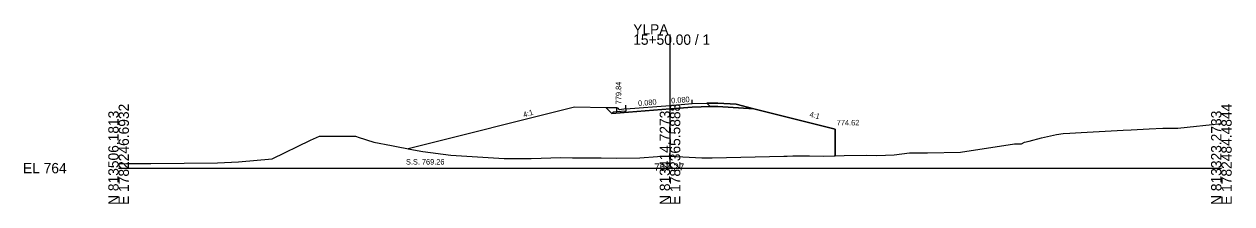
# Model space of a CAD drawing. Extents: x -76 to 1303, y -10 to 9544.
# Drawn here: x -25.7 to 302.8, y 5490.3 to 5539.1 of the extents above; entities that cross this region are included whole.
import ezdxf

# ---------------------------------------------------------------- set-up
doc = ezdxf.new("R2010")
doc.units = 0
for name, color, linetype in [('Exist Cross Section Cell', 7, 'Continuous'), ('Exist XS Center Line Elevation Label', 7, 'Continuous'), ('Exist XS Ground Line', 7, 'Continuous'), ('Prop XS Ditch Standard Text', 7, 'Continuous'), ('Prop XS Dump Level', 7, 'Continuous'), ('Prop XS Earthwork Shape', 7, 'Continuous'), ('Prop XS EOT Tick Mark', 7, 'Continuous'), ('Prop XS Finish Grade', 7, 'Continuous'), ('Prop XS Finish Grade CurbGutter', 7, 'Continuous'), ('Prop XS Finish Grade Earthwork', 7, 'Continuous'), ('Prop XS Finish Grade Paved Shoulder', 7, 'Continuous'), ('Prop XS Finish Grade Pavement', 7, 'Continuous'), ('Prop XS Hydro Elevations', 7, 'Continuous'), ('Prop XS Pvmt Edge Slope', 7, 'Continuous'), ('Prop XS SE Text', 7, 'Continuous'), ('Prop XS Side Slope Text', 7, 'Continuous'), ('Prop XS SS Elevation Text', 7, 'Continuous'), ('Prop XS Subgrade CurbGutter', 7, 'Continuous'), ('Prop XS Subgrade Earthwork', 7, 'Continuous'), ('Scratch_Level_3', 7, 'Continuous')]:
    doc.layers.add(name, color=color, linetype=linetype)

msp = doc.modelspace()

# ---------------------------------------------------------------- linework, layer by layer
at = {"layer": 'Exist Cross Section Cell'}
for p, q in [((150, 5500), (150, 5536.3)), ((0, 5500), (150, 5500)), ((150, 5500), (300, 5500))]:
    msp.add_line(p, q, dxfattribs=at)
at = {"layer": 'Exist XS Ground Line'}
for p, q in [((256.92, 5509.44), (258.78, 5509.54)), ((258.78, 5509.54), (261.81, 5509.67)), ((261.81, 5509.67), (273.27, 5510.29)), ((273.27, 5510.29), (275.48, 5510.38)), ((275.48, 5510.38), (280.32, 5510.7)), ((280.32, 5510.7), (284.08, 5510.81)), ((284.08, 5510.81), (288.15, 5510.88)), ((288.15, 5510.88), (300, 5512.1)), ((41.74, 5502.55), (52.24, 5507.59)), ((52.24, 5507.59), (54.61, 5508.71)), ((54.61, 5508.71), (61.86, 5508.71)), ((61.86, 5508.71), (63.69, 5508.7)), ((63.69, 5508.7), (64.43, 5508.7)), ((64.43, 5508.7), (64.75, 5508.57)), ((64.75, 5508.57), (65.2, 5508.42)), ((65.2, 5508.42), (69.47, 5507.03)), ((69.47, 5507.03), (74.22, 5506.14)), ((229.04, 5504.33), (243.68, 5506.61)), ((243.68, 5506.61), (245.62, 5506.64)), ((245.62, 5506.64), (246.41, 5507.03)), ((246.41, 5507.03), (247.68, 5507.33)), ((247.68, 5507.33), (251.09, 5508.22)), ((251.09, 5508.22), (255.13, 5509.13)), ((255.13, 5509.13), (256.92, 5509.44)), ((74.22, 5506.14), (80.22, 5504.98)), ((80.22, 5504.98), (82.73, 5504.51)), ((82.73, 5504.51), (90.39, 5503.56)), ((90.39, 5503.56), (104.91, 5502.66)), ((141.76, 5502.81), (146.6, 5503.19)), ((146.6, 5503.19), (149.46, 5503.3)), ((149.46, 5503.3), (150, 5503.27)), ((150, 5503.27), (158.63, 5502.82)), ((161.5, 5502.76), (181, 5503.28)), ((181, 5503.28), (181.88, 5503.29)), ((181.88, 5503.29), (183.37, 5503.33)), ((183.37, 5503.33), (185.74, 5503.36)), ((185.74, 5503.36), (186.65, 5503.34)), ((186.65, 5503.34), (187.93, 5503.36)), ((187.93, 5503.36), (191.81, 5503.29)), ((191.81, 5503.29), (197.41, 5503.42)), ((197.41, 5503.42), (203.45, 5503.54)), ((203.45, 5503.54), (206.3, 5503.43)), ((206.3, 5503.43), (211, 5503.64)), ((211, 5503.64), (215.19, 5504.15)), ((215.19, 5504.15), (220.07, 5504.19)), ((220.07, 5504.19), (229.04, 5504.33)), ((0, 5501.13), (2.18, 5501.3)), ((2.18, 5501.3), (4.11, 5501.29)), ((4.11, 5501.29), (8.77, 5501.26)), ((8.77, 5501.26), (26.94, 5501.41)), ((26.94, 5501.41), (32.66, 5501.69)), ((32.66, 5501.69), (41.74, 5502.55)), ((104.91, 5502.66), (112.19, 5502.6)), ((112.19, 5502.6), (120.31, 5502.91)), ((120.31, 5502.91), (123.44, 5502.82)), ((123.44, 5502.82), (128.06, 5502.82)), ((128.06, 5502.82), (131.3, 5502.8)), ((131.3, 5502.8), (135.47, 5502.67)), ((135.47, 5502.67), (141.76, 5502.81)), ((158.63, 5502.82), (160.12, 5502.8)), ((160.12, 5502.8), (161.5, 5502.76))]:
    msp.add_line(p, q, dxfattribs=at)
at = {"layer": 'Prop XS Dump Level'}
for p, q in [((138, 5516.08), (150, 5517.04)), ((150, 5517.04), (156, 5517.52))]:
    msp.add_line(p, q, dxfattribs=at)
at = {"layer": 'Prop XS Earthwork Shape'}
msp.add_lwpolyline([(128.06, 5502.82), (131.3, 5502.8), (135.47, 5502.67), (141.76, 5502.81), (146.6, 5503.19), (149.46, 5503.3), (150, 5503.27), (158.63, 5502.82), (160.12, 5502.8), (161.5, 5502.76), (181, 5503.28), (181.88, 5503.29), (183.37, 5503.33), (185.74, 5503.36), (186.65, 5503.34), (187.93, 5503.36), (191.81, 5503.29), (194.95, 5503.36), (194.95, 5510.62), (172.83, 5516.15), (162.98, 5516.74), (160.9, 5516.7), (156.05, 5516.6), (150.07, 5516.12), (134.16, 5514.85), (132.61, 5516.4), (124, 5516.58), (78.74, 5505.26), (80.22, 5504.98), (82.73, 5504.51), (90.39, 5503.56), (104.91, 5502.66), (112.19, 5502.6), (120.31, 5502.91), (123.44, 5502.82)], close=True, dxfattribs=at)
at = {"layer": 'Prop XS EOT Tick Mark'}
for p, q in [((138, 5516.08), (138, 5517.08)), ((156, 5517.52), (156, 5518.52))]:
    msp.add_line(p, q, dxfattribs=at)
at = {"layer": 'Prop XS Finish Grade'}
for p, q in [((135.5, 5516.34), (132.61, 5516.4)), ((160, 5517.6), (163, 5517.66)), ((163, 5517.66), (168, 5517.36)), ((168, 5517.36), (172.83, 5516.15))]:
    msp.add_line(p, q, dxfattribs=at)
at = {"layer": 'Prop XS Finish Grade CurbGutter'}
for p, q in [((135.5, 5516.34), (135.75, 5516.34)), ((135.75, 5516.34), (135.88, 5516.32)), ((135.97, 5516.23), (135.88, 5516.32)), ((136.03, 5515.98), (135.97, 5516.23)), ((138, 5516.08), (136.25, 5515.87)), ((136.13, 5515.89), (136.03, 5515.98)), ((136.25, 5515.87), (136.13, 5515.89))]:
    msp.add_line(p, q, dxfattribs=at)
at = {"layer": 'Prop XS Finish Grade Earthwork'}
for p, q in [((124, 5516.58), (78.74, 5505.26)), ((132.61, 5516.4), (124, 5516.58)), ((172.83, 5516.15), (194.95, 5510.62)), ((194.95, 5510.62), (194.95, 5503.36))]:
    msp.add_line(p, q, dxfattribs=at)
at = {"layer": 'Prop XS Finish Grade Paved Shoulder'}
msp.add_line((156, 5517.52), (160, 5517.6), dxfattribs=at)
at = {"layer": 'Prop XS Finish Grade Pavement'}
for p, q in [((138, 5516.08), (150, 5517.04)), ((150, 5517.04), (156, 5517.52))]:
    msp.add_line(p, q, dxfattribs=at)
at = {"layer": 'Prop XS Pvmt Edge Slope'}
for p, q in [((160, 5517.6), (160.9, 5516.7)), ((134.5, 5515.22), (134.16, 5514.85)), ((135.5, 5515.3), (134.5, 5515.22))]:
    msp.add_line(p, q, dxfattribs=at)
at = {"layer": 'Prop XS Subgrade CurbGutter'}
for p, q in [((135.5, 5515.3), (135.5, 5516.34)), ((138, 5516.08), (138, 5515.5)), ((138, 5515.5), (135.5, 5515.3))]:
    msp.add_line(p, q, dxfattribs=at)
at = {"layer": 'Prop XS Subgrade Earthwork'}
for p, q in [((134.16, 5514.85), (132.61, 5516.4)), ((134.16, 5514.85), (150.07, 5516.12)), ((150.07, 5516.12), (156.05, 5516.6)), ((156.05, 5516.6), (160.9, 5516.7)), ((160.9, 5516.7), (162.98, 5516.74)), ((162.98, 5516.74), (172.83, 5516.15))]:
    msp.add_line(p, q, dxfattribs=at)
at = {"layer": 'Scratch_Level_3'}
for p, q in [((163, 5517.66), (160, 5517.6)), ((160, 5517.6), (160.9, 5516.7)), ((160.9, 5516.7), (162.98, 5516.74)), ((162.98, 5516.74), (172.83, 5516.15)), ((168, 5517.36), (163, 5517.66)), ((172.83, 5516.15), (168, 5517.36))]:
    msp.add_line(p, q, dxfattribs=at)

# ---------------------------------------------------------------- texts
at = {"layer": 'Exist Cross Section Cell'}
for s, p in [('YLPA', (140, 5536.3)), ('15+50.00 / 1', (140, 5533.5)), ('EL 764', (-26, 5498.6))]:
    msp.add_text(s, height=2.8, dxfattribs=at).set_placement(p)
for s, p in [('E 1782246.6932', (2.8, 5490)), ('E 1782365.5888', (152.8, 5490)), ('E 1782484.4844', (302.8, 5490)), ('N 813506.1813', (0, 5490)), ('N 813414.7273', (150, 5490)), ('N 813323.2733', (300, 5490))]:
    msp.add_text(s, height=2.8, rotation=90, dxfattribs=at).set_placement(p)
at = {"layer": 'Exist XS Center Line Elevation Label'}
msp.add_text('767.27', height=2, dxfattribs=at).set_placement((145.7, 5499.27))
at = {"layer": 'Prop XS Ditch Standard Text'}
msp.add_text('774.62', height=1.5, dxfattribs=at).set_placement((195.36, 5511.6))
at = {"layer": 'Prop XS Dump Level'}
msp.add_text('Case4', height=0.04, dxfattribs=at).set_placement((168, 5517.32))
at = {"layer": 'Prop XS Hydro Elevations'}
msp.add_text('779.84', height=1.5, rotation=90, dxfattribs=at).set_placement((136.75, 5517.34))
at = {"layer": 'Prop XS SE Text'}
for p in [(150.38, 5517.57), (141.38, 5516.85)]:
    msp.add_text('0.080', height=1.5, rotation=4.5739, dxfattribs=at).set_placement(p)
at = {"layer": 'Prop XS Side Slope Text'}
for rotation, p in [(17.8228, (110.31, 5513.72)), (345.9638, (187.85, 5513.94))]:
    msp.add_text('4:1', height=1.5, rotation=rotation, dxfattribs=at).set_placement(p)
at = {"layer": 'Prop XS SS Elevation Text'}
msp.add_text('S.S. 769.26', height=1.5, dxfattribs=at).set_placement((78.17, 5500.96))

doc.saveas('drawing.dxf')
